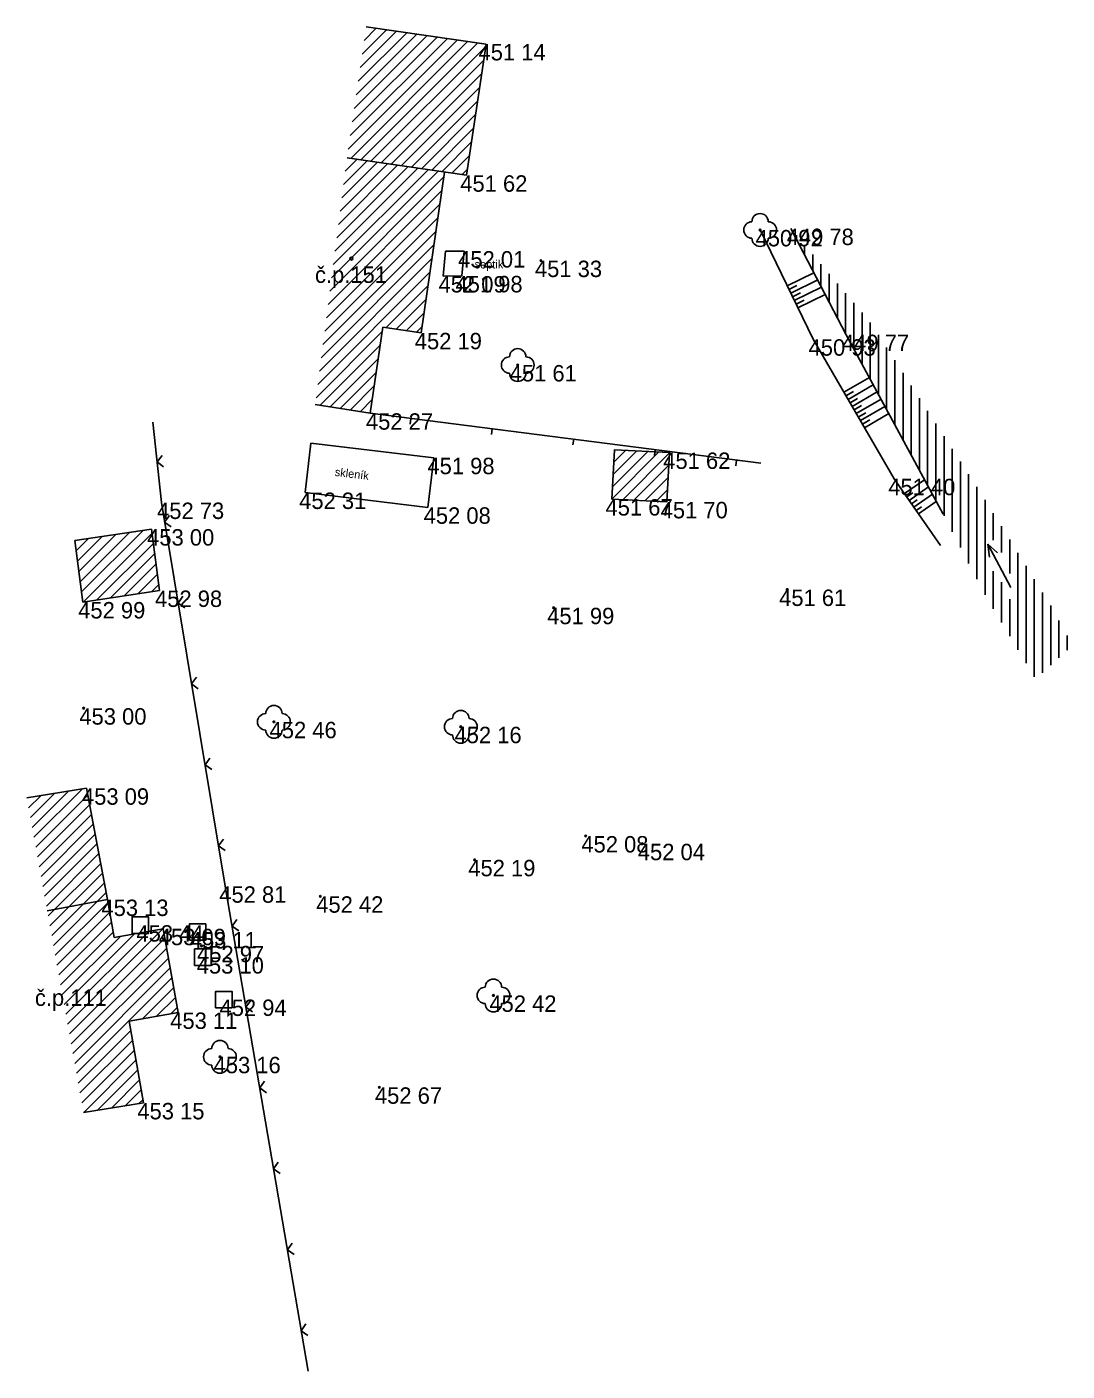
# Model space of a CAD drawing. Extents: x -554123 to -553118, y -1076825 to -1073672.
# Drawn here: x -553866.4 to -553803.1, y -1075090.1 to -1075008.2 of the extents above; entities that cross this region are included whole.
import ezdxf

# ---------------------------------------------------------------- set-up
doc = ezdxf.new("R2010")
doc.units = 0
for name, color, linetype in [('1', 7, 'Continuous'), ('12', 7, 'Continuous'), ('14', 7, 'Continuous'), ('18', 7, 'Continuous'), ('26', 7, 'Continuous'), ('27', 7, 'Continuous'), ('28', 7, 'Continuous'), ('32', 7, 'Continuous'), ('34', 7, 'Continuous'), ('47', 7, 'Continuous'), ('50', 7, 'Continuous'), ('52', 7, 'Continuous'), ('54', 7, 'Continuous'), ('6', 7, 'Continuous')]:
    doc.layers.add(name, color=color, linetype=linetype)

# ---------------------------------------------------------------- blocks, each defined once
blk = doc.blocks.new('VOTOK')
at = {"layer": '28'}
for p, q in [((-3.001, 0), (0, 0)), ((-0.75, 0.282), (0, 0)), ((0, 0), (-0.75, -0.28))]:
    blk.add_line(p, q, dxfattribs=at)
blk = doc.blocks.new('POINT_DISPLAY')
blk.add_line((0, 0), (0, 0))
blk = doc.blocks.new('STL')
at = {"layer": '34'}
blk.add_circle((0, 0), 0.05, dxfattribs=at)
for centre, start, end in [((0, 0.5), 0, 180), ((-0.5, 0), 90, 270), ((0.5, 0), 270, 90), ((0, -0.5), 180, 0)]:
    blk.add_arc(centre, 0.5, start, end, dxfattribs=at)
blk = doc.blocks.new('SA')
at = {"layer": '50'}
blk.add_lwpolyline([(-0.5, -0.5), (0.5, -0.5), (0.5, 0.5), (-0.5, 0.5)], close=True, dxfattribs=at)
blk = doc.blocks.new('T')
at = {"layer": '6'}
blk.add_circle((0, 0), 0.05, dxfattribs=at)
blk = doc.blocks.new('BZ')
at = {"layer": '47'}
blk.add_circle((0, 0), 0.0875, dxfattribs=at)

msp = doc.modelspace()

# ---------------------------------------------------------------- linework, layer by layer
at = {"layer": '12'}
for p, q in [((-553858.25, -1075037.22), (-553858.77, -1075032.32)), ((-553845.52, -1075031.78), (-553821.72, -1075034.82)), ((-553843.04, -1075032.097), (-553843.084, -1075032.444)), ((-553838.08, -1075032.73), (-553838.125, -1075033.077)), ((-553833.121, -1075033.364), (-553833.165, -1075033.711)), ((-553828.161, -1075033.997), (-553828.205, -1075034.344)), ((-553858.514, -1075034.734), (-553858.199, -1075034.345)), ((-553858.514, -1075034.734), (-553858.124, -1075035.049)), ((-553823.201, -1075034.631), (-553823.246, -1075034.978)), ((-553854.35, -1075060.6), (-553858.25, -1075037.22)), ((-553858.052, -1075038.407), (-553857.761, -1075037.999)), ((-553858.052, -1075038.407), (-553857.645, -1075038.698)), ((-553857.229, -1075043.339), (-553856.938, -1075042.931)), ((-553857.229, -1075043.339), (-553856.822, -1075043.629)), ((-553856.407, -1075048.27), (-553856.116, -1075047.863)), ((-553856.407, -1075048.27), (-553855.999, -1075048.561)), ((-553855.584, -1075053.202), (-553855.293, -1075052.795)), ((-553855.584, -1075053.202), (-553855.177, -1075053.493)), ((-553854.761, -1075058.134), (-553854.47, -1075057.727)), ((-553854.761, -1075058.134), (-553854.354, -1075058.425)), ((-553849.31, -1075090.14), (-553854.35, -1075060.6)), ((-553853.935, -1075063.032), (-553853.646, -1075062.623)), ((-553853.935, -1075063.032), (-553853.527, -1075063.321)), ((-553853.094, -1075067.961), (-553852.805, -1075067.552)), ((-553853.094, -1075067.961), (-553852.686, -1075068.25)), ((-553852.253, -1075072.889), (-553851.964, -1075072.481)), ((-553852.253, -1075072.889), (-553851.845, -1075073.179)), ((-553851.412, -1075077.818), (-553851.123, -1075077.41)), ((-553851.412, -1075077.818), (-553851.004, -1075078.107)), ((-553850.571, -1075082.747), (-553850.282, -1075082.338)), ((-553850.571, -1075082.747), (-553850.163, -1075083.036)), ((-553849.73, -1075087.676), (-553849.441, -1075087.267)), ((-553849.73, -1075087.676), (-553849.322, -1075087.965))]:
    msp.add_line(p, q, dxfattribs=at)
at = {"layer": '14'}
for p, q in [((-553845.77, -1075008.236), (-553838.45, -1075009.28)), ((-553838.45, -1075009.28), (-553839.65, -1075017.28)), ((-553839.65, -1075017.28), (-553846.933, -1075016.214)), ((-553840.986, -1075017.084), (-553842.42, -1075026.88)), ((-553844.753, -1075026.539), (-553845.52, -1075031.78)), ((-553844.753, -1075026.539), (-553842.42, -1075026.88)), ((-553848.874, -1075031.246), (-553845.52, -1075031.78)), ((-553830.63, -1075034), (-553830.8, -1075037.01)), ((-553827.28, -1075034.17), (-553830.63, -1075034)), ((-553827.28, -1075034.17), (-553827.45, -1075037.18)), ((-553827.45, -1075037.18), (-553830.8, -1075037.01)), ((-553863.52, -1075039.54), (-553858.85, -1075038.84)), ((-553858.36, -1075042.58), (-553858.85, -1075038.84)), ((-553863.03, -1075043.28), (-553863.52, -1075039.54)), ((-553863.03, -1075043.28), (-553858.36, -1075042.58)), ((-553866.444, -1075055.215), (-553862.81, -1075054.63)), ((-553861.53, -1075061.41), (-553862.81, -1075054.63)), ((-553865.214, -1075062.095), (-553861.53, -1075061.41)), ((-553861.122, -1075063.719), (-553861.53, -1075061.41)), ((-553861.122, -1075063.719), (-553858.13, -1075063.19)), ((-553857.23, -1075068.29), (-553858.13, -1075063.19)), ((-553860.22, -1075068.819), (-553857.23, -1075068.29)), ((-553859.34, -1075073.8), (-553860.22, -1075068.819)), ((-553862.993, -1075074.378), (-553859.34, -1075073.8))]:
    msp.add_line(p, q, dxfattribs=at)
at = {"layer": '18'}
for p, q in [((-553840.93, -1075021.91), (-553841.08, -1075023.42)), ((-553839.79, -1075021.9), (-553840.93, -1075021.91)), ((-553839.79, -1075021.9), (-553839.94, -1075023.41)), ((-553839.94, -1075023.41), (-553841.08, -1075023.42)), ((-553849.13, -1075033.59), (-553849.48, -1075036.61)), ((-553841.65, -1075034.49), (-553849.13, -1075033.59)), ((-553841.65, -1075034.49), (-553842, -1075037.51)), ((-553842, -1075037.51), (-553849.48, -1075036.61))]:
    msp.add_line(p, q, dxfattribs=at)
at = {"layer": '26'}
for p, q in [((-553820.114, -1075024.004), (-553818.481, -1075023.212)), ((-553820.005, -1075024.229), (-553819.513, -1075023.991)), ((-553819.896, -1075024.454), (-553818.25, -1075023.655)), ((-553819.677, -1075024.904), (-553818.018, -1075024.099)), ((-553819.786, -1075024.679), (-553819.291, -1075024.439)), ((-553819.568, -1075025.129), (-553819.068, -1075024.887)), ((-553819.459, -1075025.354), (-553817.787, -1075024.543)), ((-553816.654, -1075030.498), (-553815.103, -1075029.597)), ((-553816.403, -1075030.931), (-553814.865, -1075030.038)), ((-553816.528, -1075030.714), (-553816.065, -1075030.445)), ((-553816.277, -1075031.147), (-553815.818, -1075030.88)), ((-553816.151, -1075031.363), (-553814.627, -1075030.478)), ((-553815.9, -1075031.795), (-553814.39, -1075030.917)), ((-553816.026, -1075031.579), (-553815.571, -1075031.314)), ((-553815.774, -1075032.011), (-553815.323, -1075031.749)), ((-553815.649, -1075032.227), (-553814.153, -1075031.357)), ((-553815.523, -1075032.444), (-553815.076, -1075032.184)), ((-553815.398, -1075032.66), (-553813.915, -1075031.798)), ((-553812.962, -1075036.674), (-553811.741, -1075035.825)), ((-553812.819, -1075036.879), (-553812.46, -1075036.629)), ((-553812.676, -1075037.084), (-553811.502, -1075036.268)), ((-553812.533, -1075037.289), (-553812.188, -1075037.049)), ((-553812.391, -1075037.495), (-553811.263, -1075036.711)), ((-553812.248, -1075037.7), (-553811.917, -1075037.47)), ((-553812.105, -1075037.905), (-553811.024, -1075037.153))]:
    msp.add_line(p, q, dxfattribs=at)
at = {"layer": '27'}
for p, q in [((-553818.53, -1075027.27), (-553821.76, -1075020.61)), ((-553813.59, -1075035.77), (-553818.53, -1075027.27)), ((-553810.76, -1075039.84), (-553813.59, -1075035.77))]:
    msp.add_line(p, q, dxfattribs=at)
at = {"layer": '28'}
for p, q in [((-553816.51, -1075026.99), (-553819.88, -1075020.53)), ((-553819.55, -1075021.163), (-553819.55, -1075020.919)), ((-553819.05, -1075022.121), (-553819.05, -1075021.507)), ((-553818.55, -1075023.079), (-553818.55, -1075022.096)), ((-553818.05, -1075024.038), (-553818.05, -1075022.685)), ((-553817.55, -1075024.996), (-553817.55, -1075023.274)), ((-553817.05, -1075025.955), (-553817.05, -1075023.862)), ((-553816.55, -1075026.913), (-553816.55, -1075024.451)), ((-553816.05, -1075027.842), (-553816.05, -1075025.04)), ((-553815.55, -1075028.768), (-553815.55, -1075025.629)), ((-553815.05, -1075029.695), (-553815.05, -1075026.238)), ((-553810.61, -1075037.92), (-553816.51, -1075026.99)), ((-553814.55, -1075030.621), (-553814.55, -1075027.009)), ((-553814.05, -1075031.547), (-553814.05, -1075027.78)), ((-553813.55, -1075032.474), (-553813.55, -1075028.551)), ((-553813.05, -1075033.4), (-553813.05, -1075029.322)), ((-553812.55, -1075034.326), (-553812.55, -1075030.093)), ((-553812.05, -1075035.252), (-553812.05, -1075030.864)), ((-553811.55, -1075036.179), (-553811.55, -1075031.634)), ((-553811.05, -1075037.105), (-553811.05, -1075032.405)), ((-553810.55, -1075038.036), (-553810.55, -1075033.176)), ((-553810.05, -1075038.998), (-553810.05, -1075033.947)), ((-553809.55, -1075039.961), (-553809.55, -1075034.718)), ((-553809.05, -1075040.923), (-553809.05, -1075035.489)), ((-553808.55, -1075041.886), (-553808.55, -1075036.26)), ((-553808.05, -1075042.848), (-553808.05, -1075037.056)), ((-553807.55, -1075039.516), (-553807.55, -1075037.861)), ((-553807.05, -1075040.269), (-553807.05, -1075038.666)), ((-553806.55, -1075041.537), (-553806.55, -1075039.471)), ((-553806.05, -1075046.183), (-553806.05, -1075040.276)), ((-553807.55, -1075043.704), (-553807.55, -1075041.39)), ((-553805.55, -1075047.009), (-553805.55, -1075041.081)), ((-553807.05, -1075044.53), (-553807.05, -1075042.069)), ((-553805.05, -1075047.835), (-553805.05, -1075041.886)), ((-553806.55, -1075045.357), (-553806.55, -1075043.101)), ((-553804.55, -1075047.589), (-553804.55, -1075042.691)), ((-553804.05, -1075047.132), (-553804.05, -1075043.496)), ((-553803.55, -1075046.674), (-553803.55, -1075044.403)), ((-553803.05, -1075046.217), (-553803.05, -1075045.32))]:
    msp.add_line(p, q, dxfattribs=at)
at = {"layer": '32'}
for p, q in [((-553846.494, -1075013.203), (-553842.057, -1075008.766)), ((-553846.373, -1075012.375), (-553842.676, -1075008.677)), ((-553846.253, -1075011.547), (-553843.295, -1075008.589)), ((-553846.132, -1075010.719), (-553843.913, -1075008.501)), ((-553846.011, -1075009.892), (-553844.532, -1075008.413)), ((-553845.891, -1075009.064), (-553845.151, -1075008.324)), ((-553846.856, -1075015.686), (-553840.2, -1075009.03)), ((-553846.735, -1075014.858), (-553840.819, -1075008.942)), ((-553846.71, -1075016.247), (-553839.582, -1075009.119)), ((-553846.615, -1075014.03), (-553841.438, -1075008.854)), ((-553846.093, -1075016.337), (-553838.963, -1075009.207)), ((-553845.476, -1075016.427), (-553838.471, -1075009.423)), ((-553844.859, -1075016.517), (-553838.596, -1075010.255)), ((-553844.242, -1075016.608), (-553838.721, -1075011.086)), ((-553843.625, -1075016.698), (-553838.846, -1075011.918)), ((-553843.008, -1075016.788), (-553838.971, -1075012.75)), ((-553842.392, -1075016.878), (-553839.095, -1075013.582)), ((-553841.775, -1075016.969), (-553839.22, -1075014.414)), ((-553841.158, -1075017.059), (-553839.345, -1075015.246)), ((-553840.541, -1075017.149), (-553839.47, -1075016.078)), ((-553847.877, -1075023.522), (-553841.381, -1075017.026)), ((-553847.772, -1075022.71), (-553841.998, -1075016.936)), ((-553847.667, -1075021.898), (-553842.615, -1075016.846)), ((-553847.562, -1075021.086), (-553843.232, -1075016.755)), ((-553847.457, -1075020.274), (-553843.849, -1075016.665)), ((-553847.352, -1075019.462), (-553844.466, -1075016.575)), ((-553847.248, -1075018.65), (-553845.082, -1075016.485)), ((-553847.143, -1075017.838), (-553845.699, -1075016.394)), ((-553847.038, -1075017.026), (-553846.316, -1075016.304)), ((-553839.924, -1075017.24), (-553839.594, -1075016.91)), ((-553847.981, -1075024.333), (-553841.03, -1075017.382)), ((-553848.086, -1075025.145), (-553841.151, -1075018.21)), ((-553848.191, -1075025.957), (-553841.272, -1075019.038)), ((-553848.296, -1075026.769), (-553841.393, -1075019.867)), ((-553848.401, -1075027.581), (-553841.515, -1075020.695)), ((-553848.506, -1075028.393), (-553841.636, -1075021.523)), ((-553848.61, -1075029.205), (-553841.757, -1075022.352)), ((-553848.715, -1075030.017), (-553841.878, -1075023.18)), ((-553844.559, -1075026.567), (-553842, -1075024.009)), ((-553843.942, -1075026.658), (-553842.121, -1075024.837)), ((-553843.325, -1075026.748), (-553842.242, -1075025.665)), ((-553848.82, -1075030.829), (-553844.791, -1075026.8)), ((-553842.708, -1075026.838), (-553842.363, -1075026.494)), ((-553848.577, -1075031.293), (-553844.912, -1075027.628)), ((-553847.967, -1075031.39), (-553845.034, -1075028.457)), ((-553847.357, -1075031.487), (-553845.155, -1075029.285)), ((-553846.747, -1075031.585), (-553845.276, -1075030.113)), ((-553846.137, -1075031.682), (-553845.397, -1075030.942)), ((-553845.527, -1075031.779), (-553845.519, -1075031.77)), ((-553830.8, -1075037.01), (-553827.927, -1075034.137)), ((-553830.758, -1075036.261), (-553828.6, -1075034.103)), ((-553830.715, -1075035.511), (-553829.273, -1075034.069)), ((-553830.673, -1075034.762), (-553829.946, -1075034.035)), ((-553830.631, -1075034.012), (-553830.619, -1075034.001)), ((-553830.127, -1075037.044), (-553827.282, -1075034.199)), ((-553829.454, -1075037.078), (-553827.324, -1075034.948)), ((-553828.781, -1075037.112), (-553827.366, -1075035.698)), ((-553828.108, -1075037.147), (-553827.409, -1075036.447)), ((-553863.192, -1075042.041), (-553860.193, -1075039.041)), ((-553863.11, -1075042.666), (-553859.361, -1075038.917)), ((-553863.015, -1075043.278), (-553858.818, -1075039.081)), ((-553863.438, -1075040.165), (-553862.688, -1075039.415)), ((-553863.356, -1075040.79), (-553861.856, -1075039.291)), ((-553863.274, -1075041.416), (-553861.025, -1075039.166)), ((-553862.183, -1075043.153), (-553858.737, -1075039.706)), ((-553861.352, -1075043.028), (-553858.655, -1075040.331)), ((-553860.52, -1075042.904), (-553858.573, -1075040.957)), ((-553859.688, -1075042.779), (-553858.491, -1075041.582)), ((-553858.856, -1075042.654), (-553858.409, -1075042.207)), ((-553866.012, -1075057.612), (-553863.073, -1075054.672)), ((-553866.336, -1075055.814), (-553865.601, -1075055.079)), ((-553866.228, -1075056.413), (-553864.758, -1075054.944)), ((-553866.12, -1075057.013), (-553863.916, -1075054.808)), ((-553865.904, -1075058.211), (-553862.733, -1075055.039)), ((-553865.797, -1075058.81), (-553862.62, -1075055.634)), ((-553865.689, -1075059.409), (-553862.508, -1075056.229)), ((-553865.581, -1075060.009), (-553862.396, -1075056.824)), ((-553865.473, -1075060.608), (-553862.284, -1075057.419)), ((-553865.365, -1075061.207), (-553862.171, -1075058.013)), ((-553865.257, -1075061.806), (-553862.059, -1075058.608)), ((-553865.149, -1075062.405), (-553861.947, -1075059.203)), ((-553865.041, -1075063.005), (-553861.834, -1075059.798)), ((-553864.933, -1075063.604), (-553861.722, -1075060.393)), ((-553864.825, -1075064.203), (-553861.61, -1075060.987)), ((-553864.717, -1075064.802), (-553861.499, -1075061.584)), ((-553864.61, -1075065.401), (-553861.393, -1075062.185)), ((-553864.502, -1075066.001), (-553861.287, -1075062.786)), ((-553864.394, -1075066.6), (-553861.181, -1075063.387)), ((-553864.286, -1075067.199), (-553860.738, -1075063.651)), ((-553864.178, -1075067.798), (-553859.879, -1075063.499)), ((-553864.07, -1075068.397), (-553859.02, -1075063.347)), ((-553863.962, -1075068.997), (-553858.161, -1075063.195)), ((-553863.854, -1075069.596), (-553858.028, -1075063.769)), ((-553863.746, -1075070.195), (-553857.922, -1075064.37)), ((-553863.638, -1075070.794), (-553857.816, -1075064.971)), ((-553863.53, -1075071.393), (-553857.71, -1075065.572)), ((-553863.423, -1075071.993), (-553857.604, -1075066.173)), ((-553859.396, -1075068.673), (-553857.497, -1075066.775)), ((-553858.537, -1075068.521), (-553857.391, -1075067.376)), ((-553857.678, -1075068.369), (-553857.285, -1075067.977)), ((-553863.315, -1075072.592), (-553860.118, -1075069.395)), ((-553863.207, -1075073.191), (-553860.012, -1075069.996)), ((-553863.099, -1075073.79), (-553859.906, -1075070.597)), ((-553862.977, -1075074.375), (-553859.8, -1075071.198)), ((-553862.137, -1075074.243), (-553859.694, -1075071.799)), ((-553861.297, -1075074.11), (-553859.587, -1075072.4)), ((-553860.457, -1075073.977), (-553859.481, -1075073.001)), ((-553859.617, -1075073.844), (-553859.375, -1075073.602))]:
    msp.add_line(p, q, dxfattribs=at)

# ---------------------------------------------------------------- block references
at = {"layer": '1'}
for p in [(-553838.45, -1075009.28), (-553839.65, -1075017.28), (-553821.76, -1075020.61), (-553819.88, -1075020.53), (-553839.79, -1075021.9), (-553835.11, -1075022.48), (-553841.08, -1075023.42), (-553839.94, -1075023.41), (-553842.42, -1075026.88), (-553818.53, -1075027.27), (-553816.51, -1075026.99), (-553836.53, -1075028.84), (-553845.52, -1075031.78), (-553827.28, -1075034.17), (-553841.65, -1075034.49), (-553813.59, -1075035.77), (-553849.48, -1075036.61), (-553858.25, -1075037.22), (-553830.8, -1075037.01), (-553827.45, -1075037.18), (-553842, -1075037.51), (-553858.85, -1075038.84), (-553858.36, -1075042.58), (-553820.11, -1075042.52), (-553863.03, -1075043.28), (-553834.34, -1075043.63), (-553862.98, -1075049.75), (-553851.39, -1075050.58), (-553840, -1075050.88), (-553862.81, -1075054.63), (-553832.39, -1075057.54), (-553828.96, -1075058.01), (-553839.16, -1075058.99), (-553854.35, -1075060.6), (-553848.56, -1075061.21), (-553861.53, -1075061.41), (-553859.53, -1075062.97), (-553858.13, -1075063.19), (-553856.04, -1075063.39), (-553855.8, -1075064.23), (-553855.72, -1075064.92), (-553854.44, -1075067.5), (-553838.01, -1075067.25), (-553857.23, -1075068.29), (-553854.68, -1075070.99), (-553844.96, -1075072.85), (-553859.34, -1075073.8)]:
    msp.add_blockref('POINT_DISPLAY', p, dxfattribs=at)
at = {"layer": '28', "xscale": 1.0000005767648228, "yscale": 1.0000005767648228, "rotation": 117.821219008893}
msp.add_blockref('VOTOK', (-553807.881, -1075039.747), dxfattribs=at)
at = {"layer": '32'}
for p in [(-553845.77, -1075008.236), (-553846.933, -1075016.214), (-553830.8, -1075037.01), (-553863.52, -1075039.54), (-553866.444, -1075055.215)]:
    msp.add_blockref('POINT_DISPLAY', p, dxfattribs=at)
at = {"layer": '34'}
for p in [(-553821.76, -1075020.61), (-553836.53, -1075028.84), (-553851.39, -1075050.58), (-553840, -1075050.88), (-553838.01, -1075067.25), (-553854.68, -1075070.99)]:
    msp.add_blockref('STL', p, dxfattribs=at)
at = {"layer": '47'}
msp.add_blockref('BZ', (-553846.67, -1075022.353), dxfattribs=at)
at = {"layer": '50'}
for p in [(-553859.53, -1075062.97), (-553856.04, -1075063.39), (-553855.72, -1075064.92), (-553854.44, -1075067.5)]:
    msp.add_blockref('SA', p, dxfattribs=at)
at = {"layer": '6'}
for p in [(-553835.11, -1075022.48), (-553820.11, -1075042.52), (-553834.34, -1075043.63), (-553862.98, -1075049.75), (-553832.39, -1075057.54), (-553828.96, -1075058.01), (-553839.16, -1075058.99), (-553848.56, -1075061.21), (-553855.8, -1075064.23), (-553844.96, -1075072.85)]:
    msp.add_blockref('T', p, dxfattribs=at)

# ---------------------------------------------------------------- texts
at = {"layer": '52'}
msp.add_text('septik', height=0.5, dxfattribs=at).set_placement((-553839.157, -1075022.955))
msp.add_text('skleník', height=0.5, rotation=353.13911, dxfattribs=at).set_placement((-553847.701, -1075035.591))
at = {"layer": '54'}
for s, p in [('č.p.151', (-553848.886, -1075023.835)), ('č.p.111', (-553865.955, -1075067.887))]:
    msp.add_text(s, height=1, dxfattribs=at).set_placement(p)
at = {"layer": '6'}
for s, p in [('451 14 ', (-553838.918, -1075010.28)), ('451 62 ', (-553840.033, -1075018.28)), ('450 92 ', (-553822.036, -1075021.61)), ('449 78 ', (-553820.14, -1075021.53)), ('452 01 ', (-553840.161, -1075022.9)), ('451 33 ', (-553835.481, -1075023.48)), ('452 09 ', (-553841.356, -1075024.42)), ('451 98 ', (-553840.323, -1075024.41)), ('452 19 ', (-553842.803, -1075027.88)), ('450 93 ', (-553818.806, -1075028.27)), ('449 77 ', (-553816.768, -1075027.99)), ('451 61 ', (-553837.02, -1075029.84)), ('452 27 ', (-553845.78, -1075032.78)), ('451 62 ', (-553827.663, -1075035.17)), ('451 98 ', (-553842.033, -1075035.49)), ('451 40 ', (-553813.951, -1075036.77)), ('452 31 ', (-553849.849, -1075037.61)), ('452 73 ', (-553858.51, -1075038.22)), ('452 08 ', (-553842.264, -1075038.51)), ('451 67 ', (-553831.181, -1075038.01)), ('451 70 ', (-553827.821, -1075038.18)), ('453 00 ', (-553859.116, -1075039.84)), ('452 98 ', (-553858.634, -1075043.58)), ('451 61 ', (-553820.6, -1075043.52)), ('452 99 ', (-553863.316, -1075044.28)), ('451 99 ', (-553834.735, -1075044.63)), ('453 00 ', (-553863.246, -1075050.75)), ('452 46 ', (-553851.652, -1075051.58)), ('452 16 ', (-553840.383, -1075051.88)), ('453 09 ', (-553863.086, -1075055.63)), ('452 08 ', (-553832.654, -1075058.54)), ('452 04 ', (-553829.212, -1075059.01)), ('452 19 ', (-553839.543, -1075059.99)), ('452 81 ', (-553854.719, -1075061.6)), ('452 42 ', (-553848.81, -1075062.21)), ('453 13 ', (-553861.901, -1075062.41)), ('453 44 ', (-553859.768, -1075063.97)), ('453 09 ', (-553858.406, -1075064.19)), ('453 11 ', (-553856.518, -1075064.39)), ('452 97 ', (-553856.072, -1075065.23)), ('453 10 ', (-553856.093, -1075065.92)), ('452 94 ', (-553854.702, -1075068.5)), ('452 42 ', (-553838.26, -1075068.25)), ('453 11 ', (-553857.708, -1075069.29)), ('453 16 ', (-553855.063, -1075071.99)), ('452 67 ', (-553845.232, -1075073.85)), ('453 15 ', (-553859.711, -1075074.8))]:
    msp.add_text(s, height=1, dxfattribs=at).set_placement(p)

doc.saveas('drawing.dxf')
